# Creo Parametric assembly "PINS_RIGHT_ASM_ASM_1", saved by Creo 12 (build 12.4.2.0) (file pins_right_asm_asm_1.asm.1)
Units: Custom; MM, KILOGRAM, SECS

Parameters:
  PTC_WM_ITERATION = "0"
  PTC_WM_VERSION = "-.0"
  PTC_WM_LIFECYCLE_STATE = "In Work"
  PTC_WM_LIFECYCLE = "MO_CADDocument"
  PTC_WM_CREATED_BY = "Maximilian Roepper (Z0017RMS: MO)"
  PTC_WM_CREATED_ON = "18-Sep-26 11:36:42 AM"
  PTC_WM_MODIFIED_BY = "Maximilian Roepper (Z0017RMS: MO)"
  PTC_WM_MODIFIED_ON = "18-Sep-26 11:36:46 AM"
  PDMLINKNUMBER = "PDM000071455040"
  PTC_WM_NUMBER = "PDM000071455040"

Other parameters: WEIGHT, WEIGHT_FACTOR, WEIGHT_ADD, MC_ERRORS, SUPPLIER

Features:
  1. coordinate system
  2. imported feature
  3. component "PIN_026_PRT_1"
  4. component "PIN_027_PRT_1"
  5. component "PIN_028_PRT_1"
  6. component "PIN_029_PRT_1"
  7. component "PIN_030_PRT_1"
  8. component "PIN_031_PRT_1"
  9. component "PIN_032_PRT_1"
  10. component "PIN_033_PRT_1"
  11. component "PIN_034_PRT_1"
  12. component "PIN_035_PRT_1"
  13. component "PIN_036_PRT_1"
  14. component "PIN_037_PRT_1"
  15. component "PIN_038_PRT_1"
  16. component "PIN_039_PRT_1"

Other named items: DRW_VIEW_ORG, ROUGH-GROB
